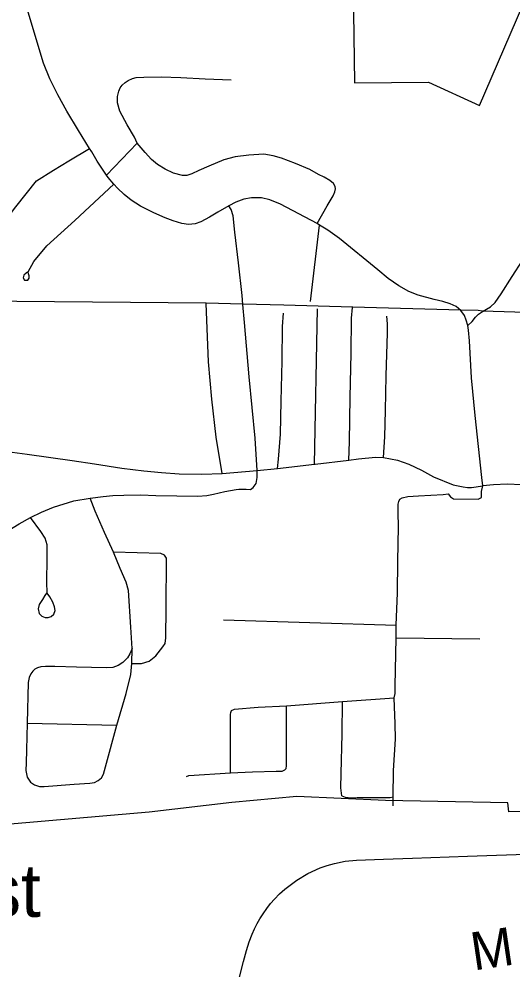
# Model space of a CAD drawing. Extents: x 2402298 to 2498138, y 789485 to 950881.
# Drawn here: x 2465309 to 2469210, y 866330 to 873839 of the extents above; entities that cross this region are included whole.
import ezdxf

# ---------------------------------------------------------------- set-up
doc = ezdxf.new("R2010")
doc.units = 0
for name, color, linetype in [('GM_X_City_Street', 7, 'Continuous'), ('GM_X_Corporation', 7, 'Continuous'), ('GM_X_County_Road', 7, 'Continuous'), ('GM_X_State_Route', 7, 'Continuous'), ('GM_X_Township', 7, 'Continuous'), ('GM_X_Township_Road', 7, 'Continuous'), ('GM_X_Township_Road_Text', 7, 'Continuous'), ('GM_X_Unincorporated_Text', 7, 'Continuous')]:
    doc.layers.add(name, color=color, linetype=linetype)

msp = doc.modelspace()

# ---------------------------------------------------------------- linework, layer by layer
at = {"layer": 'GM_X_City_Street'}
for p, q in [((2465998.8, 872605.7), (2466242.3, 872860.1)), ((2467611.4, 871609.8), (2467682.5, 872212.5)), ((2467641.1, 870323.5), (2467666.4, 871551.8)), ((2466924.7, 869094.1), (2468286.9, 869052.2)), ((2468288.3, 868952.7), (2468946.8, 868944.2)), ((2465373.7, 868279.6), (2466081.2, 868262))]:
    msp.add_line(p, q, dxfattribs=at)
for points in [[(2467663.2, 872224.6), (2467741.9, 872362.9), (2467788.6, 872444.1), (2467802.8, 872473.9), (2467808.9, 872497.6), (2467804.9, 872517.9), (2467791.3, 872539.5), (2467764.2, 872563.9), (2467718.9, 872589.6), (2467674.2, 872612), (2467604.5, 872649.9), (2467490.8, 872697.9), (2467381.8, 872740.6), (2467315.5, 872759.5), (2467241.7, 872771.7), (2467122.6, 872765.6), (2467015.6, 872750.7), (2466927, 872727.7), (2466808.5, 872677.6), (2466729.3, 872643.1), (2466674.5, 872616.7), (2466633.2, 872603.2), (2466600.7, 872602.5), (2466527.6, 872622.8), (2466462.1, 872654.4), (2466403.5, 872690.8), (2466355.7, 872729.1), (2466304.5, 872786.4), (2466242.3, 872860.1), (2466220.3, 872907.1), (2466161.7, 873002.9), (2466105.3, 873112.2), (2466087.7, 873177.1), (2466087, 873226.6), (2466095.8, 873270.6), (2466106.6, 873295.6), (2466124.2, 873317.9), (2466146.5, 873337.6), (2466170.9, 873354.5), (2466204.1, 873370.7), (2466233.9, 873377.5), (2466295.4, 873379.3), (2466432.2, 873382.2), (2466587.3, 873377), (2466778.1, 873368.4), (2466983.1, 873358.5)], [(2464989.9, 871609.3), (2465004.9, 871702.2), (2465024.7, 871783.4), (2465062.9, 871937.7), (2465098.2, 872079), (2465150.9, 872186.4), (2465282.5, 872357.1), (2465447.9, 872560.7), (2465581.4, 872646.8), (2465702.8, 872720.3), (2465866.3, 872817.6)], [(2465374.6, 871839.8), (2465364, 871831.8), (2465347.6, 871817.5), (2465342, 871796.7), (2465351.9, 871776.9), (2465377.5, 871776.9), (2465388.7, 871792.2), (2465389.2, 871812.2), (2465383.1, 871827), (2465381.7, 871842.9), (2465426.2, 871924.2), (2465528.7, 872049), (2465750.2, 872247.3), (2466057.9, 872534.5)], [(2467188.2, 870274.8), (2467172.7, 870529.3), (2467125.3, 871013.9), (2467088.7, 871443), (2467076.1, 871584.9), (2467069.8, 871655.6), (2467041.4, 871912.8), (2467014.3, 872156.4), (2466999.4, 872285.7), (2466983.1, 872336.5), (2466966.7, 872364.8)], [(2466914.1, 870250.4), (2466865.7, 870538.3), (2466831.5, 870836.3), (2466805.3, 871132.4), (2466786.7, 871592.9)], [(2467914.5, 870354.6), (2467918.2, 870500.7), (2467925, 870853.3), (2467931.4, 871197), (2467935.1, 871478.1), (2467942.6, 871560.8), (2467943.3, 871568.1)], [(2467349.3, 870291), (2467357.8, 870362.6), (2467372.7, 870561.6), (2467380.1, 870822.9), (2467386.2, 871137.6), (2467390.3, 871411), (2467398.2, 871516.7)], [(2468188, 870376.3), (2468198.6, 870539.4), (2468202.7, 870749.2), (2468209.4, 871022.7), (2468217.9, 871361.1), (2468219.9, 871431.2), (2468214.5, 871491.8)], [(2468262.2, 867627.1), (2468262.9, 867696.8), (2468265.3, 867903.9), (2468280.9, 868151.6), (2468280.5, 868276.9), (2468274.8, 868406.8), (2468272.1, 868480.2), (2468278.1, 868512.4), (2468280.5, 868571.3), (2468288.3, 868952.7), (2468286.9, 869052.2), (2468297.8, 869308), (2468300.7, 869559), (2468306.4, 869830.1), (2468302.3, 869942.4), (2468303, 869984.1), (2468304, 870007.4), (2468307.4, 870029.4), (2468317.2, 870047), (2468334.8, 870059.2), (2468378.2, 870068.3), (2468463.4, 870074.8), (2468659.4, 870084.8), (2468697.6, 870090.2), (2468717.3, 870065.8), (2468740.3, 870049.5), (2468934.5, 870048.9), (2468961.6, 870060.4), (2468960.2, 870109.1), (2468970.2, 870152)], [(2466202.7, 868867.4), (2466190.5, 869036.6), (2466172.3, 869327.7), (2466155.3, 869392), (2466108, 869501), (2466054.4, 869629.3), (2465984.2, 869784.8), (2465911, 869953.1), (2465871.7, 870056)], [(2465526.9, 869306.7), (2465511.7, 869288.1), (2465493.7, 869256.6), (2465468.7, 869215), (2465459.2, 869180.8), (2465468, 869145.3), (2465487.6, 869123.9), (2465516.4, 869112.8), (2465538.5, 869113.5), (2465563.1, 869120.6), (2465583.1, 869138.8), (2465594.2, 869167.6), (2465589.5, 869196.4), (2465575.6, 869233.3), (2465551.3, 869275.6), (2465530.3, 869305.7), (2465528.2, 869394), (2465530.6, 869579.5), (2465529.9, 869686.1), (2465515, 869740.2), (2465481.2, 869793.7), (2465400.6, 869903.3)], [(2466200.7, 868751), (2466274.8, 868750), (2466335.7, 868767.6), (2466390.2, 868810.9), (2466445, 868881.6), (2466462.6, 868909), (2466469.4, 868952.4), (2466470.4, 869187.6), (2466472.1, 869580.8), (2466458.6, 869605.5), (2466428.5, 869619.4), (2466054.4, 869629.3)], [(2466202.7, 868867.4), (2466184.5, 868827.5), (2466165.5, 868796), (2466128.3, 868758.8), (2466091, 868734.1), (2466050.8, 868718.8), (2465998.3, 868715.1), (2465763.4, 868720.2), (2465590.2, 868725.3), (2465518.1, 868727), (2465480.5, 868723.9), (2465454.8, 868715.1), (2465434.5, 868705), (2465418.2, 868690.1), (2465402.1, 868669.2), (2465389.1, 868640.3), (2465381.4, 868600.7), (2465373.7, 868279.6), (2465367.5, 868068), (2465364.1, 867964.8), (2465363.1, 867905.6), (2465373.6, 867851.8), (2465398.6, 867813.9), (2465430.4, 867792.9), (2465470.7, 867780), (2465506.6, 867778.7), (2465743.8, 867797), (2465867.7, 867806.1), (2465903.6, 867811.5), (2465934.7, 867825), (2465960.4, 867848.4), (2465976, 867877.5), (2465991.2, 867934), (2466081.2, 868262), (2466155, 868513.4), (2466190.9, 868663), (2466200.7, 868751), (2466202.7, 868867.4)], [(2466987.4, 868378.4), (2467011.1, 868389.2), (2467196.5, 868404.8), (2467420.9, 868416.6), (2467863.2, 868451.1), (2468272.1, 868480.2)], [(2467407.5, 867910), (2467417.3, 867922.2), (2467421.4, 867940.8), (2467421.4, 868016.6), (2467420.9, 868416.6)], [(2467857.5, 867705.9), (2467850.4, 867767.9), (2467852.1, 867882.6), (2467859.8, 868192.6), (2467863.2, 868451.1)], [(2466979.6, 867887.4), (2466977.6, 868203.1), (2466978.6, 868346.6), (2466980.3, 868363.5), (2466987.4, 868378.4)], [(2466631.2, 867857.9), (2466648.8, 867865.7), (2466979.6, 867887.4), (2467152, 867893.7), (2467340.2, 867901), (2467385.5, 867899.8), (2467407.5, 867910)], [(2467857.5, 867705.9), (2467884.2, 867693.4), (2467931.3, 867689.7), (2467980, 867690.7), (2468163.4, 867692.4), (2468239.6, 867692.4), (2468262.9, 867696.8)]]:
    msp.add_lwpolyline(points, dxfattribs=at)
at = {"layer": 'GM_X_Corporation'}
for points in [[(2467923.7, 875742.8), (2467958.1, 873334.8), (2468541.4, 873340.1), (2468944.7, 873157.5), (2469436.8, 874298.7)], [(2469460.8, 867584.1), (2469177.1, 867578.6), (2469170.2, 867650.6), (2468202.7, 867668.4), (2467503.1, 867699.8), (2466990.2, 867651.2), (2466335.7, 867576.8), (2465146.1, 867473.5), (2465156.8, 869762.8), (2465157.8, 869974.7), (2465196.7, 871613), (2464995.1, 871612.5), (2464026.3, 871645.6), (2464043.2, 872140.6), (2463344.2, 872919.5), (2463647.3, 873166.8), (2463406.4, 873483.1), (2462511.5, 873484.8), (2462527.1, 874308.5)]]:
    msp.add_lwpolyline(points, dxfattribs=at)
at = {"layer": 'GM_X_County_Road'}
for points in [[(2464970.2, 870458.9), (2465215.2, 870424.4), (2465372.5, 870402.3)], [(2465372.5, 870402.3), (2465727.6, 870352.6), (2465905.6, 870326.2), (2466120.8, 870293.7), (2466294.1, 870272.7), (2466434.2, 870257.8), (2466574.3, 870249.1), (2466751.7, 870246.3), (2466914.1, 870250.4), (2467188.2, 870274.8), (2467349.3, 870291), (2467641.1, 870323.5), (2467646.1, 870324.1)], [(2467646.1, 870324.1), (2467914.5, 870354.6), (2467989, 870365.5), (2468125, 870378.3), (2468188, 870376.3), (2468296.4, 870356.8), (2468386.3, 870324.2), (2468486.5, 870277.5), (2468583.2, 870224.7), (2468736.8, 870161.4), (2468817.2, 870145), (2468850.3, 870140.8), (2468881.3, 870140.4), (2468970.2, 870152)], [(2467043.7, 870125.5), (2467102.3, 870126.5), (2467136.1, 870125.2), (2467157.1, 870140.8), (2467182.1, 870172.6), (2467189.6, 870219.9), (2467188.2, 870274.8)], [(2465216, 869795.5), (2465309.9, 869852.9), (2465400.6, 869903.3), (2465486.3, 869946), (2465580, 869983.9), (2465741, 870034.2), (2465871.7, 870056), (2465974.3, 870069.9), (2466050.1, 870077), (2466136.7, 870080.7), (2466270.7, 870081.4), (2466389.2, 870077), (2466721.2, 870070.4), (2466791.3, 870076.3), (2466843.5, 870086.3), (2466934.4, 870108.3), (2467022.4, 870125.2), (2467043.7, 870125.5)], [(2467041.4, 866241), (2467082.5, 866396.3), (2467105.4, 866483.5), (2467126.5, 866551), (2467148.9, 866612.7), (2467169, 866656), (2467189.5, 866697.8), (2467210.7, 866734.3), (2467235.6, 866774.2), (2467265.7, 866816), (2467295.3, 866854.7), (2467326.6, 866890.3), (2467366.8, 866930.9), (2467407.6, 866968), (2467503.3, 867040.4), (2467588.2, 867093.1), (2467688.1, 867135.9), (2467742.6, 867155.3), (2467800.6, 867171.5), (2467885.2, 867188.5), (2467974, 867197.8), (2468186.5, 867205.4), (2468417.3, 867213.1), (2468849.7, 867228.4), (2469387.6, 867246.5)]]:
    msp.add_lwpolyline(points, dxfattribs=at)
at = {"layer": 'GM_X_State_Route'}
for points in [[(2468970.2, 870152), (2468963.8, 870218.2), (2468912, 870709.7), (2468881.6, 871006.7), (2468866.1, 871298.8), (2468858.4, 871382.5), (2468853, 871420.2), (2468840.9, 871462.3), (2468826, 871499.5), (2468799, 871537), (2468760.4, 871568.5), (2468714, 871591.4), (2468655.9, 871609.3), (2468586.8, 871625.5), (2468459.8, 871659.1), (2468387.5, 871687.2), (2468308, 871731.7), (2468225, 871791.2), (2468141.5, 871859.1), (2467840.7, 872106.5), (2467748.3, 872172.3), (2467682.5, 872212.5), (2467663.2, 872224.6), (2467374.9, 872377.4), (2467288.3, 872411.7), (2467224, 872426.3), (2467144.7, 872426.3), (2467084.7, 872415.6), (2467019.9, 872391.9), (2466966.7, 872364.8), (2466879.1, 872313.6), (2466812.4, 872273.4), (2466743.2, 872237.1), (2466698.7, 872221.7), (2466646, 872217.3), (2466594.7, 872224.1), (2466526.5, 872244.9), (2466462.7, 872270.5), (2466373.2, 872308.2), (2466267.8, 872361.4), (2466194.2, 872408.8), (2466138.1, 872453.8), (2466086.4, 872502.7), (2466057.9, 872534.5), (2466012.9, 872588.3), (2465998.8, 872605.7), (2465926.3, 872717.9), (2465882.8, 872790.5), (2465866.3, 872817.6), (2465779.2, 872959.8), (2465686.9, 873112.1), (2465614.3, 873240.8), (2465552.9, 873366.5), (2465503.1, 873491.8), (2465379.7, 873892.8)], [(2469276.3, 870161.7), (2469164, 870165.8), (2469057, 870160.4), (2468970.2, 870152)]]:
    msp.add_lwpolyline(points, dxfattribs=at)
at = {"layer": 'GM_X_Township'}
msp.add_lwpolyline([(2478122.4, 871331.4), (2475264.5, 871386.2), (2475224.5, 871387), (2474415.9, 871412.9), (2474352.1, 871403.7), (2474322.4, 871404.2), (2472192.6, 871453.1), (2469651.1, 871511.4), (2468967.7, 871531.4), (2468934.1, 871536.6), (2468798, 871539.9), (2467941.6, 871563.7), (2467399.3, 871578.7), (2467075, 871587.8), (2466785.7, 871595.8), (2464988.8, 871612.2), (2461420.7, 871696.8), (2460458.8, 871708.7), (2460429.8, 871709.1), (2460401.3, 871709.4), (2459688.5, 871718)], dxfattribs=at)
at = {"layer": 'GM_X_Township_Road'}
msp.add_lwpolyline([(2468853, 871420.2), (2468888.5, 871450), (2468913.6, 871485.7), (2468936.5, 871507.7), (2468961.8, 871524.4), (2468968.7, 871528.5), (2469031.7, 871566.1), (2469069.2, 871601.4), (2469117.4, 871668.9), (2469203.5, 871806.2), (2469284.3, 871933.7), (2469400.4, 872116.5), (2469463.7, 872214.8), (2469488.8, 872236.8), (2469530.8, 872254.9), (2469856.3, 872374.5), (2470026.7, 872445), (2470171.2, 872512.6), (2470323.7, 872575.9), (2470399.2, 872611.6), (2470407.7, 872617.4)], dxfattribs=at)

# ---------------------------------------------------------------- texts
at = {"layer": 'GM_X_Township_Road_Text'}
msp.add_text('M', height=300, rotation=8.43043, dxfattribs=at).set_placement((2468899.9, 866325.4))
at = {"layer": 'GM_X_Unincorporated_Text'}
msp.add_text('Forest', height=417, rotation=0.00001, dxfattribs=at).set_placement((2463899.5, 866749.3))

doc.saveas('drawing.dxf')
